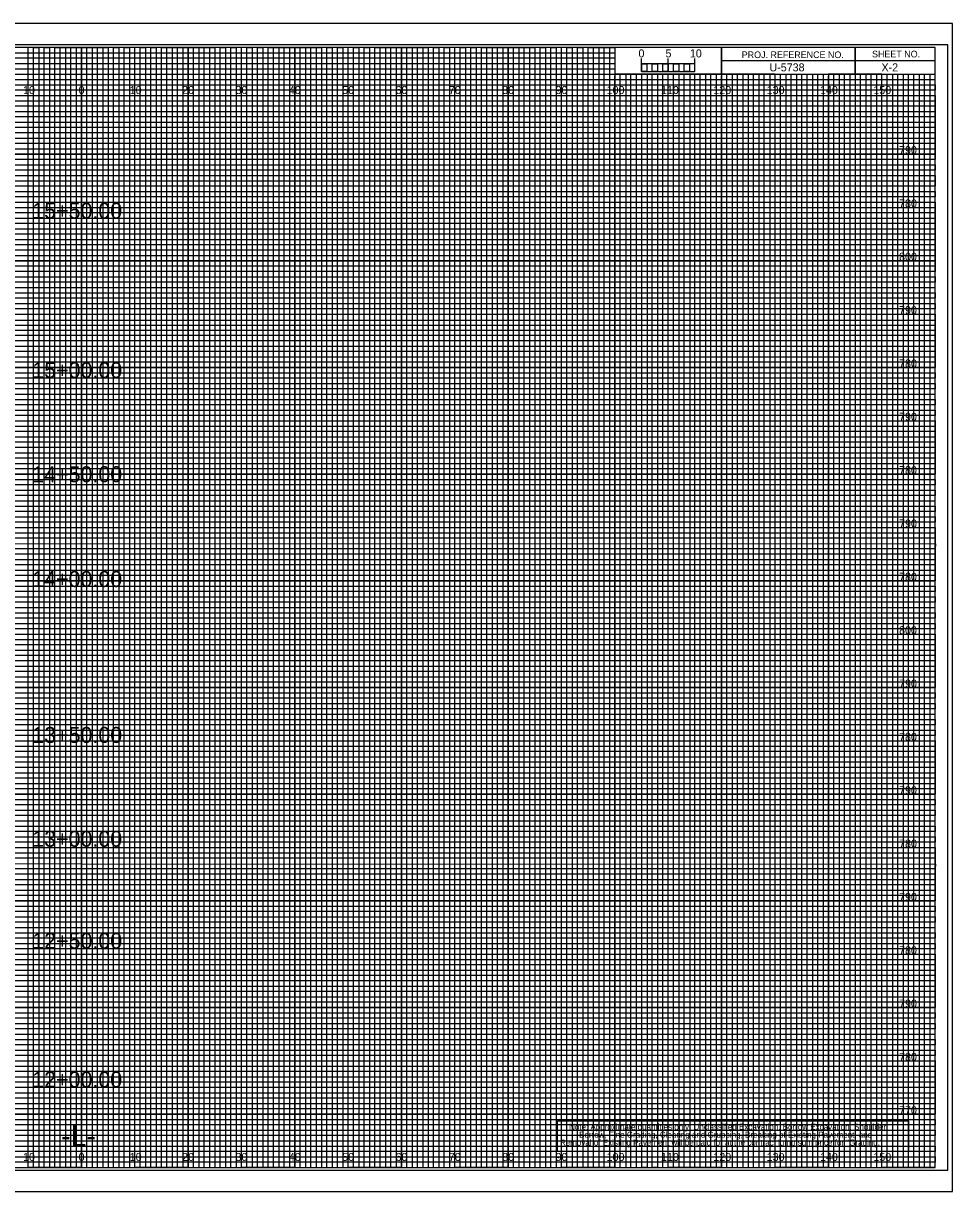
# Model space of a CAD drawing. Extents: x -13 to 323, y -5 to 215.
# Drawn here: x 149.1 to 323.3, y -4.5 to 214.5 of the extents above; entities that cross this region are included whole.
import ezdxf

# ---------------------------------------------------------------- set-up
doc = ezdxf.new("R2010")
doc.units = 0
for name, color, linetype in [('Prop CMT Conc Surface', 7, 'Continuous'), ('Prop XS Earthwork Shape', 7, 'Continuous'), ('Prop XS Elevation Labels', 7, 'Continuous'), ('Prop XS Label Text', 7, 'Continuous'), ('Prop XS Offset Labels', 7, 'Continuous'), ('Prop XS Project Number', 7, 'Continuous'), ('Prop XS Sheet Number', 7, 'Continuous'), ('Prop XS Side Slope Text', 7, 'Continuous'), ('Prop XS Station Labels', 7, 'Continuous'), ('Sheet Cross Section CELL', 7, 'Continuous'), ('Sheet Cross Section Grid Major CELL', 7, 'Continuous'), ('Sheet Cross Section Grid Middle CELL', 7, 'Continuous'), ('Sheet Cross Section Grid Minor 1 CELL', 7, 'Continuous'), ('Sheet Cross Section Grid Minor 2 CELL', 7, 'Continuous'), ('Sheet Cross Section Scale CELL', 7, 'Continuous'), ('Sheet Cutting Line CELL', 7, 'Continuous'), ('Sheet DOT Grid CELL', 7, 'Continuous'), ('Sheet Plot Border Inside CELL', 7, 'Continuous'), ('Sheet Plot Border Outside CELL', 7, 'Continuous')]:
    doc.layers.add(name, color=color, linetype=linetype)

msp = doc.modelspace()

# ---------------------------------------------------------------- linework, layer by layer
at = {"layer": 'Prop CMT Conc Surface'}
msp.add_lwpolyline([(249.25, 8.77), (315, 8.77), (315, 3), (249.25, 3)], close=True, dxfattribs=at)
at = {"layer": 'Prop XS Label Text'}
for p, q in [((150, 210), (140, 210)), ((150, 0), (150, 210)), ((170, 210), (160, 210)), ((160, 210), (160, 0)), ((170, 0), (170, 210)), ((190, 210), (180, 210)), ((180, 210), (180, 0)), ((190, 0), (190, 210)), ((210, 210), (200, 210)), ((200, 210), (200, 0)), ((210, 0), (210, 210)), ((230, 210), (220, 210)), ((220, 210), (220, 0)), ((230, 0), (230, 210)), ((250, 210), (240, 210)), ((240, 210), (240, 0)), ((250, 0), (250, 210)), ((260, 210), (260, 0)), ((270, 0), (270, 205)), ((290, 205), (280, 205)), ((280, 205), (280, 0)), ((290, 0), (290, 205)), ((310, 205), (300, 205)), ((300, 205), (300, 0)), ((310, 0), (310, 205)), ((160, 0), (150, 0)), ((180, 0), (170, 0)), ((200, 0), (190, 0)), ((220, 0), (210, 0)), ((240, 0), (230, 0)), ((260, 0), (250, 0)), ((280, 0), (270, 0)), ((300, 0), (290, 0)), ((320, 0), (310, 0)), ((320, 0), (320, 0))]:
    msp.add_line(p, q, dxfattribs=at)
for points in [[(0, 200), (320, 200), (320, 190), (0, 190)], [(0, 180), (320, 180), (320, 170), (0, 170)], [(0, 160), (320, 160), (320, 150), (0, 150)], [(0, 140), (320, 140), (320, 130), (0, 130)], [(0, 120), (320, 120), (320, 110), (0, 110)], [(0, 100), (320, 100), (320, 90), (0, 90)], [(0, 80), (320, 80), (320, 70), (0, 70)], [(0, 60), (320, 60), (320, 50), (0, 50)], [(0, 40), (320, 40), (320, 30), (0, 30)], [(0, 20), (320, 20), (320, 10), (0, 10)]]:
    msp.add_lwpolyline(points, dxfattribs=at)
at = {"layer": 'Prop XS Offset Labels'}
for points in [[(145, 0), (155, 0), (155, 210), (165, 210), (165, 0), (175, 0), (175, 210), (185, 210), (185, 0), (195, 0), (195, 210), (205, 210), (205, 0), (215, 0), (215, 210), (225, 210), (225, 0), (235, 0), (235, 210), (245, 210), (245, 0), (255, 0), (255, 210), (259.93, 210), (260, 210), (260, 205), (264.99, 205), (264.99, 0), (275, 0), (275, 205), (285, 205), (285, 0), (295, 0), (295, 205), (305, 205), (305, 0), (315, 0), (315, 205)], [(0, 205), (275, 205)], [(0, 185), (320, 185), (320, 195), (0, 195)], [(0, 165), (320, 165), (320, 175), (0, 175)], [(0, 145), (320, 145), (320, 155), (0, 155)], [(0, 125), (320, 125), (320, 135), (0, 135)], [(0, 105), (320, 105), (320, 115), (0, 115)], [(0, 85), (320, 85), (320, 95), (0, 95)], [(0, 65), (320, 65), (320, 75), (0, 75)], [(0, 45), (320, 45), (320, 55), (0, 55)], [(0, 25), (320, 25), (320, 35), (0, 35)], [(0, 5), (320, 5), (320, 15), (0, 15)]]:
    msp.add_lwpolyline(points, dxfattribs=at)
at = {"layer": 'Sheet Cross Section CELL'}
for p, q in [((265, 205.49), (265, 207.9)), ((265, 206.9), (265, 207.9)), ((270, 205.49), (270, 207.9)), ((275, 205.49), (275, 207.9)), ((275, 206.9), (275, 207.9))]:
    msp.add_line(p, q, dxfattribs=at)
for points in [[(275, 206.9), (265, 206.9), (265, 205.49), (275, 205.49)], [(265, 206.9), (266, 206.9), (266, 205.49), (265, 205.49)], [(267, 206.9), (268, 206.9), (268, 205.49), (267, 205.49)], [(269, 206.9), (270, 206.9), (270, 205.49), (269, 205.49)], [(271, 206.9), (272, 206.9), (272, 205.49), (271, 205.49)], [(273, 206.9), (274, 206.9), (274, 205.49), (273, 205.49)]]:
    msp.add_lwpolyline(points, close=True, dxfattribs=at)
at = {"layer": 'Sheet Cross Section Grid Major CELL'}
for p, q in [((0, 209), (260, 209)), ((260, 209), (260, 207.98)), ((260, 207.98), (0, 207.98)), ((0, 207), (260, 207)), ((260, 205.89), (0, 205.89)), ((260, 207), (260, 205.89)), ((0, 204), (320, 204))]:
    msp.add_line(p, q, dxfattribs=at)
for points in [[(0, 203), (270, 203), (320, 203), (320, 202), (0, 202)], [(0, 201), (320, 201), (320, 199), (0, 199)], [(0, 198), (320, 198), (320, 197), (0, 196.98)], [(0, 196), (320, 196), (320, 194), (0, 194)], [(0, 193), (320, 193), (320, 192), (0, 192)], [(0, 191), (320, 191), (320, 189), (0, 189)], [(0, 188), (320, 188), (320, 187), (0, 187)], [(0, 186), (320, 186), (320, 184), (0, 184)], [(0, 183), (320, 183), (320, 182), (0, 182)], [(0, 181), (320, 181), (320, 179), (0, 179)], [(0, 178), (320, 178), (320, 177), (0, 177)], [(0, 176), (320, 176), (320, 173.95), (320, 173), (320, 172), (0, 172)], [(0, 174), (320, 174), (320, 173), (0, 173)], [(0, 171), (320, 171), (320, 169), (0, 169.03)], [(0, 169.03), (320, 169), (320, 168), (0, 168)], [(0, 167), (320, 167), (320, 166), (0, 166)], [(0, 164), (320, 164), (320, 163), (0, 163)], [(0, 162), (320, 162), (320, 161), (0, 161)], [(-0.07, 158.89), (320, 158.89), (320, 157.88), (-0.07, 157.88)], [(0, 157), (320, 157), (320, 156), (0, 156)], [(0, 154), (320, 154), (320, 153), (0, 153)], [(0, 152), (320, 152), (320, 151), (0, 151)], [(0, 149), (320, 149), (320, 148), (0, 148)], [(0, 147), (320, 147), (320, 146), (0, 146)], [(0, 144), (320, 144), (320, 143), (0, 143)], [(0, 142), (320, 142), (320, 141), (0, 141)], [(0, 139), (320, 139), (319.99, 137.98), (0, 138)], [(0, 137), (320, 137), (320, 136), (0, 136)], [(0, 134), (320, 134), (320, 133), (0, 133)], [(0, 132), (320, 132), (320, 131), (0, 131)], [(0, 129), (320, 129), (320, 128), (0, 128)], [(0, 127), (320, 127), (320, 126), (0, 126)], [(0, 124), (320, 124), (320, 123), (0, 123)], [(0, 122), (320, 122), (320, 121), (0, 121)], [(0, 119), (320, 119), (320, 118), (0, 118)], [(0, 116.99), (320.07, 116.91), (320, 116), (0, 116)], [(0, 114), (320, 114), (320, 113), (0, 113)], [(0, 112), (320, 112), (320, 111), (0, 111)], [(0, 109), (320, 109), (320, 108), (0, 108)], [(0, 107), (320, 107), (320, 106), (0, 106)], [(0, 104), (320, 104), (320, 103), (0, 103)], [(0, 102), (320, 102), (320, 101), (0, 101)], [(0, 99), (320, 99), (320, 98), (0, 98)], [(0, 97), (320, 97), (320, 96), (0, 96)], [(0, 94), (320, 94), (320, 93), (0, 93)], [(0, 92), (320, 92), (320, 91), (0, 91)], [(0, 89), (320, 89), (320, 88), (0, 88)], [(0, 87), (320, 87), (320, 86), (0, 86)], [(0, 84), (320, 84), (320, 83), (0, 83)], [(0, 82), (320, 82), (320, 81), (0, 81)], [(0, 79), (320, 79), (319.99, 77.98), (0, 78)], [(0, 77), (320, 77), (320, 76), (0, 76)], [(0, 74), (320, 74), (320, 73), (0, 73)], [(0, 72), (320, 72), (320, 71), (0, 71)], [(0, 69), (320, 69), (320, 68), (0, 68)], [(0, 67), (320, 67), (320, 66), (0, 66)], [(0, 64), (320, 64), (320, 63), (0, 63)], [(0, 62), (320, 62), (320, 61), (0, 61)], [(0, 59), (320, 59), (320, 58), (0, 58)], [(0, 56.99), (320.07, 56.91), (320, 56), (0, 56)], [(0, 54), (320, 54), (320, 53), (0, 53)], [(0, 52), (320, 52), (320, 51), (0, 51)], [(0, 49), (320, 49), (320, 48), (0, 48)], [(0, 47), (320, 47), (320, 46), (0, 46)], [(0, 44), (320, 44), (320, 43), (0, 43)], [(0, 42), (320, 42), (320, 41), (0, 41)], [(0, 39), (320, 39), (320, 38), (0, 38)], [(0, 37), (320, 37), (320, 36), (0, 36)], [(0, 34), (320, 34), (320, 33), (0, 33)], [(0, 32), (320, 32), (320, 31), (0, 31)], [(0, 29), (320, 29), (320, 28), (0, 28)], [(0, 27), (320, 27), (320, 26), (0, 26)], [(0, 24), (320, 24), (320, 23), (0, 23)], [(0, 22), (320, 22), (320, 21), (0, 21)], [(0, 19), (320, 19), (320, 18), (0, 18)], [(0, 17), (320, 17), (320, 16), (0, 16)], [(0, 14), (320, 14), (320, 13), (0, 13)], [(0, 12), (320, 12), (320, 11), (0, 11)], [(0, 9), (320, 9), (320, 8), (0, 8)], [(0, 7), (320, 7), (320, 6), (0, 6)], [(0, 4), (320, 4), (320, 3), (0, 3)], [(0, 2), (320, 2), (320, 1), (0, 1)]]:
    msp.add_lwpolyline(points, dxfattribs=at)
at = {"layer": 'Sheet Cross Section Grid Middle CELL'}
for p, q in [((305, 210), (305, 205)), ((305, 205), (305, 210)), ((280, 207.5), (280, 205)), ((320, 207.49), (280, 207.49)), ((280, 205), (320, 205))]:
    msp.add_line(p, q, dxfattribs=at)
for points in [[(320, 210), (0, 210), (0, 0), (320, 0)], [(280, 210), (260, 210), (260, 205.03), (280, 205.03)], [(320, 210), (280, 210), (280, 205), (320, 205)]]:
    msp.add_lwpolyline(points, close=True, dxfattribs=at)
at = {"layer": 'Sheet Cross Section Grid Minor 1 CELL'}
for p, q in [((267, 205), (266.01, 205)), ((266.01, 205), (266.01, 0)), ((267, 0), (267, 205)), ((269, 205), (268, 205)), ((268, 205), (268, 0)), ((269, 0), (269, 205)), ((266.01, 0), (265, 0)), ((268, 0), (267, 0))]:
    msp.add_line(p, q, dxfattribs=at)
for points in [[(150, 0), (151, 0), (151, 210), (152, 210), (152, 0)], [(152, 0), (153, 0), (153, 210), (154, 210), (154, 0)], [(155, 0), (156, 0), (156, 210), (157, 210), (157, 0)], [(157, 0), (158, 0), (158, 210), (159, 210), (159, 0)], [(160, 0), (161, 0), (161, 210), (162, 210), (162, 0)], [(162, 0), (163, 0), (163, 210), (164, 210), (164, 0)], [(165, 0), (166, 0), (166, 210), (167, 210), (167, 0)], [(167, 0), (168, 0), (168, 210), (169, 210), (169, 0)], [(170, 0), (171, 0), (171, 210), (172, 210), (172, 0)], [(172, 0), (173, 0), (173, 210), (174, 210), (174, 0)], [(175, 0), (176, 0), (176, 210), (177, 210), (177, 0)], [(177, 0), (178, 0), (178, 210), (179, 210), (179, 0)], [(180, 0), (181, 0), (181, 210), (182, 210), (182, 0)], [(182, 0), (183, 0), (183, 210), (184, 210), (184, 0)], [(185, 0), (186, 0), (186, 210), (187, 210), (187, 0)], [(187, 0), (188, 0), (188, 210), (189, 210), (189, 0)], [(190, 0), (191, 0), (191, 210), (192, 210), (192, 0)], [(192, 0), (193, 0), (193, 210), (194, 210), (194, 0)], [(195, 0), (196, 0), (196, 210), (197, 210), (197, 0)], [(197, 0), (198, 0), (198, 210), (199, 210), (199, 0)], [(200, 0), (201, 0), (201, 210), (202, 210), (202, 0)], [(202, 0), (203, 0), (203, 210), (204, 210), (204, 0)], [(205, 0), (206, 0), (206, 210), (207, 210), (207, 0)], [(207, 0), (208, 0), (208, 210), (209, 210), (209, 0)], [(210, 0), (211, 0), (211, 210), (212, 210), (212, 0)], [(212, 0), (213, 0), (213, 210), (214, 210), (214, 0)], [(215, 0), (216, 0), (216, 210), (217, 210), (217, 0)], [(217, 0), (218, 0), (218, 210), (219, 210), (219, 0)], [(220, 0), (221, 0), (221, 210), (222, 210), (222, 0)], [(222, 0), (223, 0), (223, 210), (224, 210), (224, 0)], [(225, 0), (226, 0), (226, 210), (227, 210), (227, 0)], [(227, 0), (228, 0), (228, 210), (229, 210), (229, 0)], [(230, 0), (231, 0), (231, 210), (232, 210), (232, 0)], [(232, 0), (233, 0), (233, 210), (234, 210), (234, 0)], [(235, 0), (236, 0), (236, 210), (237, 210), (237, 0)], [(237, 0), (238, 0), (238, 210), (239, 210), (239, 0)], [(240, 0), (241, 0), (241, 210), (242, 210), (242, 0)], [(242, 0), (243, 0), (243, 210), (244, 210), (244, 0)], [(245, 0), (246, 0), (246, 210), (247, 210), (247, 0)], [(247, 0), (248, 0), (248, 210), (249, 210), (249, 0)], [(250, 0), (251, 0), (251, 210), (252, 210), (252, 0)], [(252, 0), (253, 0), (253, 210), (254, 210), (254, 0)], [(255, 0), (256, 0), (256, 210), (257, 210), (257, 0)], [(257, 0), (258, 0), (258, 210), (259, 210), (259, 0)], [(260, 0), (261, 0), (261, 205), (262.02, 205), (262.02, 0)], [(262, 0), (263, 0), (263, 205), (263.99, 205), (263.99, 0)], [(270, 0), (270.98, 0), (270.98, 205), (272, 205), (272, 0)], [(272, 0), (273, 0), (273, 205), (274.05, 205), (274.05, 0)], [(275, 0), (276, 0), (276, 205), (277, 205), (277, 0)], [(277, 0), (278, 0), (278, 205), (279, 205), (279, 0)], [(280, 0), (281, 0), (281, 205), (282, 205), (282, 0)], [(282, 0), (283, 0), (283, 205), (284, 205), (284, 0)], [(285, 0), (286, 0), (286, 205), (287, 205), (287, 0)], [(287, 0), (288, 0), (288, 205), (289, 205), (289, 0)], [(290, 0), (291, 0), (291, 205), (292, 205), (292, 0)], [(292, 0), (293, 0), (293, 205), (294, 205), (294, 0)], [(295, 0), (296, 0), (296, 205), (297, 205), (297, 0)], [(297, 0), (298, 0), (298, 205), (299, 205), (299, 0)], [(300, 0), (301, 0), (301, 205), (302, 205), (302, 0)], [(302, 0), (303, 0), (303, 205), (304, 205), (304, 0)], [(305, 0), (306, 0), (306, 205), (307, 205), (307, 0)], [(307, 0), (308, 0), (308, 205), (309, 205), (309, 0)], [(310, 0), (311, 0), (311, 205), (312, 205), (312, 0)], [(312, 0), (313, 0), (313, 205), (314, 205), (314, 0)], [(315, 0), (316, 0), (316, 205), (317, 205), (317, 0)], [(317, 0), (318, 0), (318, 205), (319, 205), (319, 0)]]:
    msp.add_lwpolyline(points, dxfattribs=at)
at = {"layer": 'Sheet Cross Section Grid Minor 2 CELL'}
msp.add_lwpolyline([(-13.4, -4.5), (323.3, -4.5), (323.3, 214.5), (-13.4, 214.5)], close=True, dxfattribs=at)
at = {"layer": 'Sheet Cross Section Scale CELL'}
msp.add_lwpolyline([(-10.8, -0.5), (322.4, -0.5), (322.4, 210.5), (-10.8, 210.5)], close=True, dxfattribs=at)
at = {"layer": 'Sheet Plot Border Inside CELL'}
for p, q in [((323.3, 214.5), (-13.4, 214.5)), ((-13.4, -4.5), (323.3, -4.5))]:
    msp.add_line(p, q, dxfattribs=at)
at = {"layer": 'Sheet Plot Border Outside CELL'}
for p, q in [((150, 0), (150, 210)), ((160, 0), (160, 210)), ((170, 0), (170, 210)), ((180, 0), (180, 210)), ((190, 0), (190, 210)), ((200, 0), (200, 210)), ((210, 0), (210, 210)), ((220, 0), (220, 210)), ((230, 0), (230, 210)), ((240, 0), (240, 210)), ((250, 0), (250, 210)), ((260, 0), (260, 204.69)), ((270, 0), (270, 204.69)), ((280, 0), (280, 204.69)), ((290, 0), (290, 204.69)), ((300, 0), (300, 204.69)), ((310, 0), (310, 204.69)), ((0, 200), (320, 200)), ((0, 190), (320, 190)), ((0, 180), (320, 180)), ((0, 170), (320, 170)), ((0, 160), (320, 160)), ((0, 150), (320, 150)), ((0, 140), (320, 140)), ((0, 130), (320, 130)), ((0, 120), (320, 120)), ((0, 110), (320, 110)), ((0, 100), (320, 100)), ((0, 90), (320, 90)), ((0, 80), (320, 80)), ((0, 70), (320, 70)), ((0, 60), (320, 60)), ((0, 50), (320, 50)), ((0, 40), (320, 40)), ((0, 30), (320, 30)), ((0, 20), (320, 20)), ((0, 10), (320, 10))]:
    msp.add_line(p, q, dxfattribs=at)

# ---------------------------------------------------------------- texts
at = {"layer": 'Prop XS Earthwork Shape'}
for s, p in [('Note: Approximate quantities only. Unclassified Excavation, Borrow Excavation, Shoulder', (251.39, 7.09)), ('Borrow, Fine Grading, Clearing and Grubbing, Breaking of Existing Pavement, and', (253.28, 5.61)), ('Removal of Existing Pavement will be paid for at the contract lump sum price for "Grading."', (249.69, 4.14))]:
    msp.add_text(s, height=1.125, dxfattribs=at).set_placement(p)
at = {"layer": 'Prop XS Elevation Labels'}
msp.add_text('X-2', height=1.5, dxfattribs=at).set_placement((309.96, 205.5))
at = {"layer": 'Prop XS Project Number'}
for s, p in [('5', (269.47, 208.12)), ('10', (274.04, 208.12))]:
    msp.add_text(s, height=1.5, dxfattribs=at).set_placement(p)
at = {"layer": 'Prop XS Sheet Number'}
msp.add_text('-L-', height=4, dxfattribs=at).set_placement((156.15, 4))
at = {"layer": 'Prop XS Side Slope Text'}
for s, p in [('10', (149.04, 201.25)), ('0', (159.45, 201.25)), ('0', (159.45, 201.25)), ('10', (169.04, 201.25)), ('20', (178.86, 201.25)), ('30', (188.86, 201.25)), ('40', (198.86, 201.25)), ('50', (208.86, 201.25)), ('60', (218.86, 201.25)), ('70', (228.86, 201.25)), ('80', (238.86, 201.25)), ('90', (248.86, 201.25)), ('100', (258.44, 201.25)), ('110', (268.62, 201.25)), ('120', (278.44, 201.25)), ('130', (288.44, 201.25)), ('140', (298.44, 201.25)), ('150', (308.44, 201.25)), ('10', (149.04, 1.25)), ('0', (159.45, 1.25)), ('0', (159.45, 1.25)), ('10', (169.04, 1.25)), ('20', (178.86, 1.25)), ('30', (188.86, 1.25)), ('40', (198.86, 1.25)), ('50', (208.86, 1.25)), ('60', (218.86, 1.25)), ('70', (228.86, 1.25)), ('80', (238.86, 1.25)), ('90', (248.86, 1.25)), ('100', (258.44, 1.25)), ('110', (268.62, 1.25)), ('120', (278.44, 1.25)), ('130', (288.44, 1.25)), ('140', (298.44, 1.25)), ('150', (308.44, 1.25))]:
    msp.add_text(s, height=1.5, dxfattribs=at).set_placement(p)
at = {"layer": 'Prop XS Station Labels'}
msp.add_text('U-5738', height=1.5, dxfattribs=at).set_placement((288.96, 205.5))
at = {"layer": 'Sheet Cross Section CELL'}
msp.add_text('0', height=1.5, dxfattribs=at).set_placement((264.41, 208.12))
at = {"layer": 'Sheet Cross Section Grid Middle CELL'}
for s, p in [('PROJ. REFERENCE NO.', (283.77, 207.99)), ('SHEET NO.', (308.19, 208.12))]:
    msp.add_text(s, height=1.25, dxfattribs=at).set_placement(p)
at = {"layer": 'Sheet Cutting Line CELL'}
for s, p in [('15+50.00', (150.77, 177.88)), ('15+00.00', (150.77, 148)), ('14+50.00', (150.77, 128.48)), ('14+00.00', (150.77, 108.84)), ('13+50.00', (150.77, 79.61)), ('13+00.00', (150.77, 60.15)), ('12+50.00', (150.77, 41.03)), ('12+00.00', (150.77, 15.02))]:
    msp.add_text(s, height=3, dxfattribs=at).set_placement(p)
at = {"layer": 'Sheet DOT Grid CELL'}
for s, p in [('790', (313.26, 190)), ('780', (313.26, 180)), ('800', (313.26, 170)), ('790', (313.26, 160)), ('780', (313.26, 150)), ('790', (313.26, 140)), ('780', (313.26, 130)), ('790', (313.26, 120)), ('780', (313.26, 110)), ('800', (313.26, 100)), ('790', (313.26, 90)), ('780', (313.26, 80)), ('790', (313.26, 70)), ('780', (313.26, 60)), ('790', (313.26, 50)), ('780', (313.26, 40)), ('790', (313.26, 30)), ('780', (313.26, 20)), ('770', (313.26, 10))]:
    msp.add_text(s, height=1.5, dxfattribs=at).set_placement(p)

doc.saveas('drawing.dxf')
